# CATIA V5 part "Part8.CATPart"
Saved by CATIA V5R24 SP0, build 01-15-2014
Part number: Botão
Bounding box of the stored display mesh (mm): x -5 to 8, y -13 to 13, z -12.803 to 12.803
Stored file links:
  C:\Users\Fatec\Downloads\Maquina componentes catia\Maquina componentes catia\Part8.CATPart
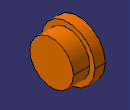
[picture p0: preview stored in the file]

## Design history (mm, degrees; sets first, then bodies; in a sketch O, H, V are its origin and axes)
Body1 (main body)
  Sketch1 on yz-plane, origin (0, 0, 0), H (0, 1, 0), V (0, 0, 1)
    circle A1 centre (0, 0) radius 10.5
    point P1 (0, 0)
    radius A1 = 10.5
    coincidence: P1 O
  Pad1: profile Sketch1, direction (1, 0, 0), length 8
  Sketch2 on start face of Pad1, origin (0, 0, 0), H (0, -1, 0), V (0, 0, 1)
    circle A1 centre (0, 0) radius 13
    radius A1 = 13
  Pad2: profile Sketch2, direction (-1, 0, 0), length 5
